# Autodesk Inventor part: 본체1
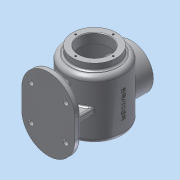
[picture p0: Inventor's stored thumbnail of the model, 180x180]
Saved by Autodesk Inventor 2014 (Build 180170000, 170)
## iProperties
Created: 2023-01
Part Number: 본체1
Material: 알루미늄 6061
Document SubType Name: Modeling
Designer: dg
Density: 2.71 g/cm^3
Appearance: 알루미늄 - 평지
Mass: 1027.11 g
Surface Area: 1161.19 cm^2
Volume: 379.006 cm^3
Author: dg
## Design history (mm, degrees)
sketch "스케치1"
  geometry: C1 r 50 at (0, 0); 1 further point
  constraints: 1 centre point, 1 coincident
  dimensions: "d0" = 100 diameter of C1
extrude "돌출1" new body sketch "스케치1" stored distance "d1" = 122; taper "d2" = 0 deg
sketch "스케치2"
  geometry: L1 (50, -61)-(-50, -61) reference; L2 (-50, -61)-(-50, 61) reference; L3 (-50, 61)-(50, 61) reference; L4 (50, 61)-(50, -61) reference; L5 (0, 61)-(0, -61); L6 (50, -50.087)-(50, -61); L7 (50, -61)-(0, -61); A1 r 120 centre (0, 59) between (0, -61) and (50, -50.087); 1 further point
  constraints: 6 end point, 3 midpoint, 2 collinear, 2 point on circle, 2 point on line, 2 tangent, 1 centre point
  dimensions: "d3" = 240 diameter of A1
revolve "회전1" sketch "스케치2" stored, may be unused: angle "d4" = 90 deg
sketch "스케치3"
  geometry: L1 (-50, -50.087)-(-50, 61) reference; L2 (-50, 61)-(50, 61) reference; L3 (50, 61)-(50, -50.087) reference; L4 (0, 61)-(0, -61); L5 (50, 49)-(38, 49); L6 (38, 49)-(38, 61); L7 (50, 49)-(50, 61); L8 (50, 61)-(38, 61); L9 (27, 61)-(27, 44); L10 (27, 44)-(42, 44); L11 (45, 41)-(45, -45.742); L12 (50, -50.087)-(-50, -50.087) reference; L13 (27, 61)-(0, 61); A1 r 120 centre (0, 59) between (0, -61) and (50, -50.087) reference; A2 r 120 centre (0, 59) between (-50, -50.087) and (0, -61) reference; A3 r 115 centre (2.337, 59) between (0, -55.976) and (43.062, -48.548); A4 r 3 centre (42, -45.742) between (43.062, -48.548) and (45, -45.742); A5 r 3 centre (42, 41) between (45, 41) and (42, 44); 2 further points
  constraints: 18 end point, 7 point on circle, 5 point on line, 4 perpendicular, 4 tangent, 3 centre point, 3 parallel, 2 collinear, 1 equal radius, 1 midpoint
  dimensions: "d5" = 76 diameter of L6 L4; "d6" = 110 distance from line of L4.end L5; "d9" = 115 radius of A3; "d10" = 90 diameter of L11 L4; "d11" = 17 distance between parallel lines of L2 L10; "d12" = 54 diameter of L9 L4; "d13" = 2 distance from line of L13 A3.centre; "d14" = 4.67494 diameter of A3.centre L4; "d15" = 3 radius of A4
revolve "회전2" sketch "스케치3" stored, may be unused: angle "d16" = 90 deg
chamfer "모따기1" distance "d17" = 1; stored, may be unused: second distance "d18" = 2, angle "d19" = 45 deg
fillet "모깎기1" dims "d20" = 8
fillet "모깎기2" dims "d21" = 3
node "작업 평면1"
sketch "스케치4"
  geometry: 1 further point
node "작업 평면2"
sketch "스케치5"
  geometry: L1 (38, 61)-(-38, 61) reference; C1 r 38 at (0, -2); A1 r 120 centre (0, 59) between (-45, -52.243) and (45, -52.243) reference; 1 further point
  constraints: 1 centre point, 1 vertical alignment
  dimensions: "d24" = 63 distance from line of C1.centre L1; "d25" = 76 diameter of C1
extrude "돌출2" join sketch "스케치5" stored distance "d26" = 122; taper "d27" = 0 deg
sketch "스케치6"
  geometry: L1 (0, 15)-(0, -19); L2 (-46, 15)-(-46, -19); L3 (46, -19)-(46, 15); L4 (-35, 3)-(35, 3); L5 (35, 3)-(35, -7); L6 (35, -7)-(-35, -7); L7 (-35, -7)-(-35, 3); L8 (-35, 3)-(35, -7); L9 (35, 3)-(-35, -7); C1 r 38 at (0, -2) reference; C2 r 38 at (0, -2) reference; A1 r 46 centre (0, 15) between (46, 15) and (-46, 15); A2 r 46 centre (0, -19) between (-46, -19) and (46, -19); 1 further point
  constraints: 20 end point, 4 point on circle, 4 tangent, 3 midpoint, 3 parallel, 2 centre point, 1 horizontal, 1 perpendicular, 1 vertical
  dimensions: "d31" = 92 distance between parallel lines of L2 L3; "d32" = 70 distance between parallel lines of L7 L5; "d33" = 10 distance of L4.end L5.end; "d34" = 34 distance of L3.start L3.end
extrude "돌출3" join sketch "스케치6" distance "d35" = 10; taper "d36" = 0 deg
fillet "모깎기3" dims "d37" = 3
sketch "스케치7"
  geometry: L1 (-35, -3)-(35, -3); L2 (35, -3)-(35, 7); L3 (35, 7)-(-35, 7); L4 (-35, 7)-(-35, -3); L5 (-35, -3)-(35, 7); L6 (35, -3)-(-35, 7); C1 r 38 at (0, 2) reference; 1 further point
  constraints: 12 end point, 2 parallel, 1 coincident, 1 horizontal, 1 midpoint, 1 perpendicular
  dimensions: "d38" = 10 distance between parallel lines of L1 L3; "d39" = 70 distance of L1.start L1.end
extrude "돌출4" join sketch "스케치7" stored distance "d40" = 10; taper "d41" = 0 deg
sketch "스케치9"
  geometry: L1 (-70, 58)-(-70, 3) reference; L2 (-70, 3)-(-50, 3) reference; L3 (-50, 3)-(-50, 41) reference; L4 (-42, 49)-(-41, 49) reference; L5 (-38, 52)-(-38, 61) reference; L6 (-38, 61)-(-28, 61) reference; L7 (-28, 61)-(-27, 60) reference; L8 (-27, 60)-(-27, 44) reference; L9 (-27, 44)-(-42, 44) reference; L10 (-45, 41)-(-45, -45.742) reference; L11 (45, -45.742)-(45, 41) reference; L12 (42, 44)-(27, 44) reference; L13 (27, 44)-(27, 60) reference; L14 (27, 60)-(28, 61) reference; L15 (28, 61)-(38, 61) reference; L16 (38, 61)-(38, 52) reference; L17 (41, 49)-(42, 49) reference; L18 (50, 41)-(50, 36) reference; L19 (50, 36)-(64, 36) reference; L20 (64, 36)-(64, -40) reference; L21 (64, -40)-(50, -40) reference; L22 (50, -40)-(50, -44.827) reference; L23 (-50, -44.827)-(-50, -7) reference; L24 (-50, -7)-(-70, -7) reference; L25 (-70, -7)-(-70, -62) reference; L26 (-73, -65)-(-80, -65) reference; L27 (-80, -65)-(-80, 61) reference; L28 (-80, 61)-(-73, 61) reference; L29 (-50, 32.641)-(-70, 38); A1 r 3 centre (-73, 58) between (-70, 58) and (-73, 61) reference; A2 r 8 centre (-42, 41) between (-42, 49) and (-50, 41) reference; A3 r 3 centre (-41, 52) between (-41, 49) and (-38, 52) reference; A4 r 3 centre (-42, 41) between (-42, 44) and (-45, 41) reference; A5 r 3 centre (-42, -45.742) between (-45, -45.742) and (-43.062, -48.548) reference; A6 r 115 centre (-2.337, 59) between (-43.062, -48.548) and (0, -55.976) reference; A7 r 115 centre (2.337, 59) between (0, -55.976) and (43.062, -48.548) reference; A8 r 3 centre (42, -45.742) between (43.062, -48.548) and (45, -45.742) reference; A9 r 3 centre (42, 41) between (45, 41) and (42, 44) reference; A10 r 3 centre (41, 52) between (38, 52) and (41, 49) reference; A11 r 8 centre (42, 41) between (50, 41) and (42, 49) reference; A12 r 8 centre (42, -44.827) between (45, -52.243) and (50, -44.827) reference; A13 r 120 centre (0, 59) between (0, -61) and (45, -52.243) reference; A14 r 120 centre (0, 59) between (-45, -52.243) and (0, -61) reference; A15 r 8 centre (-42, -44.827) between (-50, -44.827) and (-45, -52.243) reference; A16 r 3 centre (-73, -62) between (-73, -65) and (-70, -62) reference; 1 further point
  constraints: 2 end point, 2 point on line
  dimensions: "d42" = 105 deg angle of L1 L29; "d98" = 23 distance from line of L28 L29.end
feature "리브1" sketch "스케치9" dims "d44" = 1, "d45" = 10, "d46" = 0, "d47" = 0, "d48" = 1, "d49" = 1
node "작업 평면3"
sketch "스케치10"
  geometry: C1 r 38 at (0, 0) reference; C2 r 27 at (0, 0); 1 further point
  constraints: 1 centre point, 1 coincident
  dimensions: "d51" = 54 diameter of C2
extrude "돌출5" cut sketch "스케치10" stored distance "d52" = 10; taper "d53" = 0 deg
sketch "스케치11" dims "d54" = 65
  geometry: C1 r 27 at (0, 0) reference; C2 r 38 at (0, 0) reference; C3 r 3.218 at (0, 32.5); 2 further points
  constraints: 2 vertical alignment, 1 centre point, 1 coincident, 2 other
hole "구멍1" sketch "스케치11" at (0, 32.5) diameter "d55" = 3.242; stored, may be unused: countersink angle "d59" = 90 deg, drill point angle "d61" = 118 deg; dims "d56" = 8, "d57" = 4, "d58" = 2, "d60" = 10
sketch "스케치12" dims "d65" = 65
  geometry: C1 r 38 at (0, 0) reference; C2 r 28 at (0, 0) reference; C3 r 3.222 at (0, 32.5); 1 further point
  constraints: 2 vertical alignment, 1 centre point, 1 coincident, 2 other
hole "구멍2" sketch "스케치12" at (0, 32.5) diameter "d66" = 3.242; stored, may be unused: countersink angle "d70" = 90 deg, drill point angle "d72" = 118 deg; dims "d67" = 8, "d68" = 4, "d69" = 2, "d71" = 10
fillet "모깎기4" dims "d76" = 3
fillet "모깎기5" dims "d77" = 3
chamfer "모따기2" distance "d78" = 1; stored, may be unused: second distance "d79" = 2, angle "d80" = 45 deg
node "작업 평면4"
sketch "스케치13"
  geometry: L1 (38, 61)-(-38, 61) reference; L2 (-80, -65)-(-80, -19) reference; 2 further points
  constraints: 1 other
  dimensions: "d82" = 63 distance from line of L1 point (0, -2); "d83" = 80 distance from line of L2 point (0, -2)
feature "엠보싱1" sketch "스케치13" dims "d5" = 76, "d6" = 110, "d9" = 115, "d10" = 90, "d11" = 17, "d12" = 54, "d13" = 2, "d14" = 4.67494, "d15" = 3, "d84" = 0.5, "d85" = 0
sketch "스케치14"
  geometry: C1 r 4.5 at (-30, -30); C2 r 4.5 at (-30, 30); C3 r 4.5 at (30, -30); C4 r 4.5 at (30, 30); 1 further point
  constraints: 4 centre point, 3 equal radius
  dimensions: "d86" = 30 horizontal distance of point (0, 0) C1.centre; "d87" = 30 horizontal distance of point (0, 0) C1.centre; "d88" = 9 diameter of C1; "d89" = 30 horizontal distance of C2.centre point (0, 0); "d90" = 30 horizontal distance of point (0, 0) C2.centre; "d91" = 30 horizontal distance of point (0, 0) C3.centre; "d92" = 30 horizontal distance of point (0, 0) C3.centre; "d93" = 30 horizontal distance of point (0, 0) C4.centre; "d94" = 30 horizontal distance of point (0, 0) C4.centre
extrude "돌출6" cut sketch "스케치14" distance "d95" = 10; taper "d96" = 0 deg
node "작업 평면5"
fillet "모깎기6" dims "d99" = 3
fillet "모깎기7" dims "d100" = 3
node "솔리드1"
pattern_circular "원형 패턴1" dims angle "d63" = 360 deg
pattern_circular "원형 패턴2" dims angle "d74" = 360 deg
mirror "대칭2"
node "투영된 루프1"
node "투영된 루프2"
node "절단 모서리 투영1"
node "절단 모서리 투영2"
node "절단 모서리 투영4"
other parameters: "d23" = 64, "d50" = 0
